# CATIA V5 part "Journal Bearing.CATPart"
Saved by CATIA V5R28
Part number: Journal Bearing
Material "Green": density 7860 kg/m3, Young's modulus 2e+11 Pa, Poisson ratio 0.266
Bounding box of the stored display mesh (mm): x -70 to 70, y -19.6 to 19.6, z -33.6 to 28
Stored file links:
  C:\Users\Parisa\Desktop\tarah sanat\Oldham Coupling\Journal Bearing.CATPart
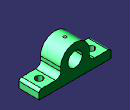
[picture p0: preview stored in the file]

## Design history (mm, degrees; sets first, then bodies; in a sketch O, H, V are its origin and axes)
Body1 (main body), material "Green"
  Sketch1 on zx-plane, origin (0, 0, 0), H (-1, 0, 0), V (0, 0, 1)
    arc A1 centre (0, 0) radius 28 from (28, 0) to (-28, 0) ccw
    circle A2 centre (0, 0) radius 14
    point P1 (28, 0)
    line L1 (28, 0) -> (28, -6.8)
    line L2 (38, -16.8) -> (65, -16.8)
    line L3 (70, -21.8) -> (70, -33.6)
    point P2 (70, -33.6)
    line L4 (70, -33.6) -> (0, -33.6)
    point P3 (0, -33.6)
    arc A3 centre (38, -6.8) radius 10 from (28, -6.8) to (38, -16.8) ccw
    point P4 (28, -6.8)
    point P5 (38, -16.8)
    arc A4 centre (65, -21.8) radius 5 from (65, -16.8) to (70, -21.8) cw
    point P7 (65, -16.8)
    point P8 (70, -21.8)
    point P10 (-28, -6.8)
    point P11 (-28, 0)
    line L5 (-28, 0) -> (-28, -6.8)
    point P12 (-70, -33.6)
    point P13 (0, -33.6)
    point P14 (-65, -16.8)
    point P15 (-70, -21.8)
    point P17 (-38, -16.8)
    line L6 (-38, -16.8) -> (-65, -16.8)
    line L7 (-70, -21.8) -> (-70, -33.6)
    line L8 (-70, -33.6) -> (0, -33.6)
    arc A5 centre (-65, -21.8) radius 5 from (-65, -16.8) to (-70, -21.8) ccw
    arc A6 centre (-38, -6.8) radius 10 from (-28, -6.8) to (-38, -16.8) cw
    radius A1 = 28
    radius A2 = 14
    radius A3 = 10
    radius A4 = 5
    distance L3 L7 = 140
    distance L4 L2 = 16.8
    distance L4 H = 33.6
    tangency: L1 A1, A3 L1, A3 L2, A4 L2, A4 L3
    horizontal: L2 H, L4 H
    vertical: L3 V, L1 V
    symmetry: P4 P10 V, P1 P11 V, L1 L5 V, P2 P12 V, P3 P13 V, P7 P14 V, P8 P15 V, P5 P17 V, L2 L6 V, L3 L7 V, L4 L8 V, A4 A5 V, A3 A6 V
    coincidence: P3 P13
  Pad1: profile Sketch1, direction (0, 1, 0), length 19.6, mirrored extent
  Sketch2 on face of Pad1 from Sketch1.L6, origin (53.682, -6.0985, -16.8), H (1, 0, 0), V (0, 1, 0)
    point P1 (-3.282, 6.0985)
    reference intersected line E1 through (0, 6.0985) direction (-1, 0) from zx-plane
    reference projected line E2 (16.318, -13.5015) -> (16.318, 25.6985) from edge [face of Pad1 from Sketch1.L7 | face of Pad1 from Sketch1.A5]
    distance E2 P1 = 19.6
    coincidence: P1 E1
  Hole1: placed by Sketch2, at (50.4, 0, -16.8) direction (0, 0, -1), diameter 14, through (limit type 3)
  Mirror1: of Hole1, about yz-plane
  Point1: type OnSurface, Support face of Pad1 from Sketch1.A1, Length 0, Direction (0.6524, 0.7508, -0.103)
  Sketch3 on {plane type Tangent, Support face of Pad1 from Sketch1.A1, RefPoint Point1}, origin (0, 0, 28), H (1, 0, 0), V (0, -1, 0)
    point P1 (0, 0)
    reference projected point E1 (0, 0) from Point1
    coincidence: E1 P1
  Hole2: placed by Sketch3, at (0, 0, 28) direction (0, 0, -1), diameter 3, through (limit type 6), countersink depth 5, countersink angle 90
